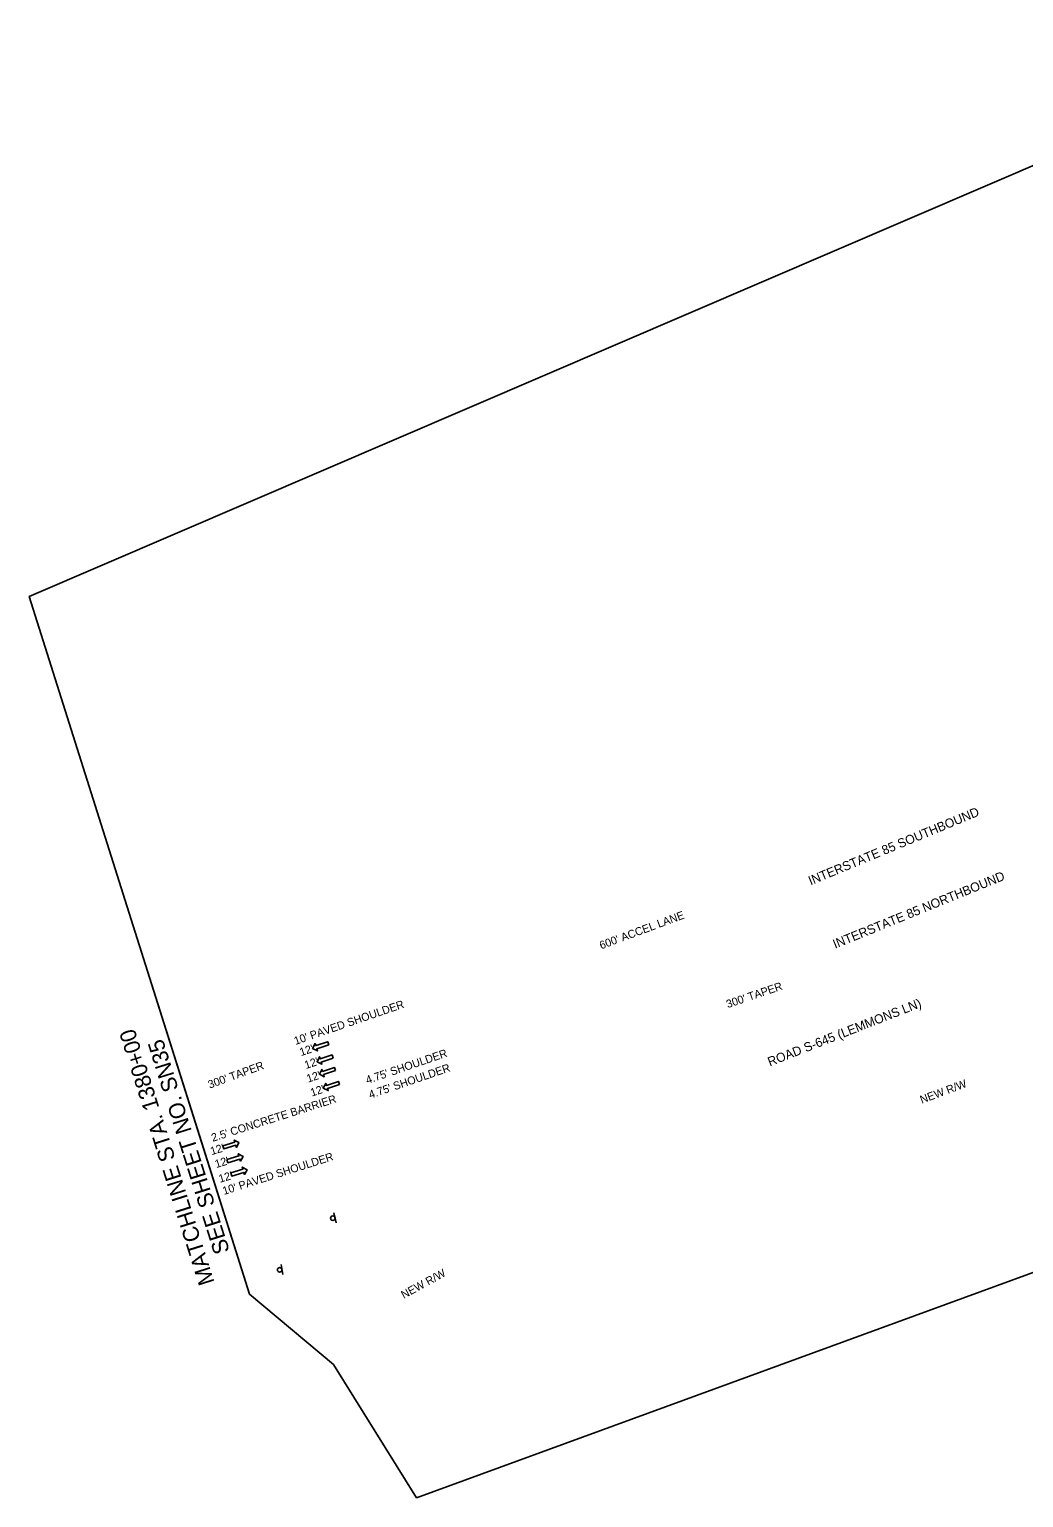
# Model space of a CAD drawing. Extents: x 1786955 to 1788674, y 1181944 to 1183335.
# Drawn here: x 1786955 to 1787825, y 1181944 to 1183228 of the extents above; entities that cross this region are included whole.
import ezdxf

# ---------------------------------------------------------------- set-up
doc = ezdxf.new("R2010")
doc.units = 0
for name, color, linetype in [('RD_PD_Final_LnLine', 7, 'Continuous'), ('RD_PD_Final_TX', 7, 'Continuous'), ('RD_PD_RW_TX', 7, 'Continuous'), ('RD_SHT_MatchLine', 7, 'Continuous'), ('RD_SHT_ShtClip', 7, 'Continuous'), ('RD_TX_RoadID', 7, 'Continuous'), ('SN_P_Signs', 7, 'Continuous')]:
    doc.layers.add(name, color=color, linetype=linetype)

# ---------------------------------------------------------------- blocks, each defined once
blk = doc.blocks.new('SARRW2')
at = {"layer": 'RD_PD_Final_LnLine'}
blk.add_lwpolyline([(-12, 1.2), (-12, -1.2), (-2.8, -1.2), (-2.8, -2.8), (0, 0), (-2.8, 2.8), (-2.8, 1.2)], close=True, dxfattribs=at)

msp = doc.modelspace()

# ---------------------------------------------------------------- linework, layer by layer
at = {"layer": 'RD_SHT_MatchLine'}
msp.add_line((1787221.1, 1182060.4), (1787147.5, 1182122.1), dxfattribs=at)
msp.add_lwpolyline([(1787147.5, 1182122.1), (1787105.4, 1182255.3), (1787036.8, 1182472.8)], dxfattribs=at)
at = {"layer": 'RD_SHT_ShtClip'}
msp.add_lwpolyline([(1788602.9, 1182624.6), (1788373.6, 1183042.3), (1788169.2, 1183137.1), (1788110.4, 1183228.5), (1786954.9, 1182732.3), (1787147.5, 1182122.1), (1787221.1, 1182060.4), (1787293.7, 1181944), (1787901.7, 1182166), (1788673.6, 1182495.9)], close=True, dxfattribs=at)
at = {"layer": 'SN_P_Signs'}
for p, q in [((1787223.3, 1182184.4), (1787221.4, 1182193.3)), ((1787176.7, 1182139.2), (1787175.1, 1182148.1))]:
    msp.add_line(p, q, dxfattribs=at)
for centre in [(1787220.4, 1182188.5), (1787173.9, 1182143.3)]:
    msp.add_circle(centre, 2, dxfattribs=at)

# ---------------------------------------------------------------- block references
at = {"layer": 'RD_PD_Final_LnLine'}
for p, xscale, yscale, rotation in [((1787202.7, 1182337), 1.1999999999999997, 1.2, -161.6143205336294), ((1787206.6, 1182325.4), 1.1999999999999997, 1.2, -161.6143205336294), ((1787208.7, 1182314.4), 1.1999999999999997, 1.2, -161.6143205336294), ((1787212.1, 1182302.2), 1.1999999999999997, 1.2, -161.6143205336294), ((1787138.3, 1182254.6), 1.2, 1.2000000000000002, 16.80308723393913), ((1787141.9, 1182242.6), 1.2, 1.2000000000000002, 16.80308723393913), ((1787145.4, 1182230.9), 1.2, 1.2000000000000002, 16.80308723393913)]:
    msp.add_blockref('SARRW2', p, dxfattribs=dict(at, xscale=xscale, yscale=yscale, rotation=rotation))

# ---------------------------------------------------------------- texts
at = {"layer": 'RD_PD_Final_TX'}
for s, rotation, p in [("600' ACCEL LANE", 20.4131, (1787455.2, 1182423.6)), ("300' TAPER", 18.7761, (1787565.9, 1182372.2)), ("10' PAVED SHOULDER", 18.9506, (1787187.8, 1182340)), ("12'", 18.3857, (1787192.6, 1182330.2)), ("300' TAPER", 20.0263, (1787112.7, 1182301.8)), ("12'", 18.3857, (1787196.9, 1182318.9)), ("4.75' SHOULDER", 18.9506, (1787250.6, 1182305.8)), ("12'", 18.3857, (1787198.8, 1182307)), ("4.75' SHOULDER", 18.9506, (1787253.2, 1182293)), ("12'", 18.3857, (1787202.1, 1182294.8)), ("2.5' CONCRETE BARRIER", 17.6852, (1787115.4, 1182255.3)), ("12'", 16.8031, (1787114.4, 1182243.6)), ("12'", 16.8031, (1787118.4, 1182232.3)), ("10' PAVED SHOULDER", 17.6852, (1787125.2, 1182208.8)), ("12'", 16.8031, (1787121.7, 1182219.4))]:
    msp.add_text(s, height=7, rotation=rotation, dxfattribs=at).set_placement(p)
at = {"layer": 'RD_PD_RW_TX'}
for rotation, p in [(20.433, (1787735.6, 1182288.6)), (28.7808, (1787282.5, 1182117.8))]:
    msp.add_text('NEW R/W', height=7, rotation=rotation, dxfattribs=at).set_placement(p)
at = {"layer": 'RD_SHT_MatchLine'}
for s, p in [('MATCHLINE STA. 1380+00', (1787117, 1182132.4)), ('SEE SHEET NO. SN35', (1787130.4, 1182159.6))]:
    msp.add_text(s, height=14, rotation=107.5135, dxfattribs=at).set_placement(p)
at = {"layer": 'RD_TX_RoadID'}
for s, rotation, p in [('INTERSTATE 85 SOUTHBOUND', 22.4872, (1787638.4, 1182479.6)), ('INTERSTATE 85 NORTHBOUND', 22.1134, (1787659.8, 1182424.2)), ('ROAD S-645 (LEMMONS LN)', 21.4044, (1787602.7, 1182321.2))]:
    msp.add_text(s, height=8, rotation=rotation, dxfattribs=at).set_placement(p)

doc.saveas('drawing.dxf')
